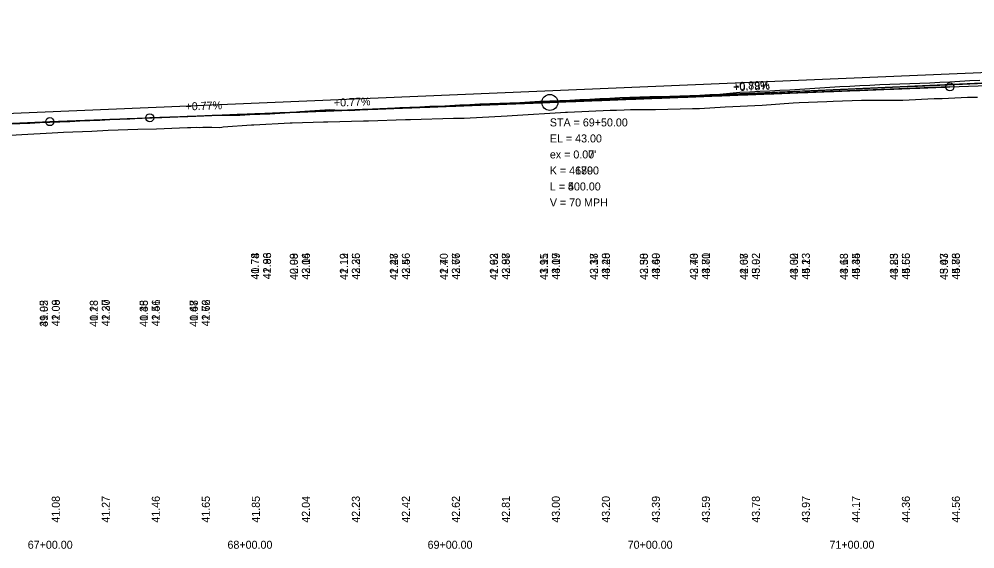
# Model space of a CAD drawing. Extents: x 3880794 to 3915434, y 287517 to 300173.
# Drawn here: x 3887223 to 3887700.8, y 296519.7 to 296784.4 of the extents above; entities that cross this region are included whole.
import ezdxf

# ---------------------------------------------------------------- set-up
doc = ezdxf.new("R2010")
doc.units = 0
for name, color, linetype in [('Level 1', 7, 'Continuous'), ('Level 2', 7, 'Continuous'), ('Level 30', 7, 'Continuous'), ('Level 31', 7, 'Continuous'), ('Level 32', 7, 'Continuous')]:
    doc.layers.add(name, color=color, linetype=linetype)

msp = doc.modelspace()

# ---------------------------------------------------------------- linework, layer by layer
at = {"layer": 'Level 1'}
for p, q in [((3887738.3, 296753.87), (3887492.29, 296742.93)), ((3887688.3, 296750.53), (3887738.3, 296752.48)), ((3887688.3, 296750.53), (3887492.29, 296742.91)), ((3887238.3, 296733.14), (3887484.3, 296742.6)), ((3887288.3, 296735.06), (3887484.3, 296742.6)), ((3886713.3, 296712.95), (3887288.3, 296735.06)), ((3886763.3, 296714.87), (3887238.3, 296733.14))]:
    msp.add_line(p, q, dxfattribs=at)
for points in [[(3887521.59, 296738.95), (3887525.37, 296739.11), (3887528.7, 296739.16), (3887541.06, 296739.28), (3887559.54, 296739.69), (3887563.11, 296739.73), (3887576.02, 296740.5), (3887579.85, 296740.74), (3887594.39, 296741.43), (3887609.96, 296742.54), (3887613.02, 296742.73), (3887626.71, 296743.21), (3887629.88, 296743.39), (3887644.18, 296743.85), (3887647.21, 296743.85), (3887661.54, 296743.9), (3887664.74, 296743.91), (3887680.5, 296744.65), (3887684.5, 296744.72), (3887697.12, 296745.32), (3887702.04, 296745.42)], [(3887215.89, 296726.2), (3887224.27, 296726.73), (3887239.4, 296727.56), (3887245.2, 296727.92), (3887259.26, 296728.43), (3887267.48, 296728.93), (3887282.24, 296729.38), (3887291.65, 296729.55), (3887303.06, 296730), (3887307.21, 296730.17), (3887308.82, 296730.29), (3887311.81, 296730.44), (3887313.02, 296730.14), (3887314.82, 296730.34), (3887316.18, 296730.38), (3887319.27, 296730.33), (3887323.29, 296730.24), (3887324.28, 296730.33), (3887324.99, 296730.5), (3887339.06, 296731.51), (3887340.27, 296731.58), (3887358.47, 296732.47), (3887359.53, 296732.51), (3887375.16, 296733.11), (3887376.6, 296732.99), (3887376.92, 296732.98), (3887377.28, 296732.98), (3887395.12, 296733.56), (3887397.71, 296733.58), (3887416.2, 296734.25), (3887418.61, 296734.25), (3887440.14, 296734.81), (3887442.95, 296734.85), (3887445.4, 296734.94), (3887466.9, 296736.07), (3887469.46, 296736.2), (3887472.12, 296736.32), (3887493.63, 296737.66), (3887496.17, 296737.89), (3887497.14, 296737.95), (3887518.43, 296738.82), (3887521.59, 296738.95)]]:
    msp.add_lwpolyline(points, dxfattribs=at)
msp.add_circle((3887488.3, 296742.76), 4, dxfattribs=at)
msp.add_circle((3887488.3, 296742.76), 4, dxfattribs=at)
for points in [[(3887238.3, 296733.14), (3887248.3, 296733.53), (3887258.3, 296733.91), (3887268.3, 296734.3), (3887278.3, 296734.69), (3887288.3, 296735.08), (3887298.3, 296735.47), (3887308.3, 296735.86), (3887318.3, 296736.26), (3887328.3, 296736.65), (3887338.3, 296737.05), (3887348.3, 296737.44), (3887358.3, 296737.84), (3887368.3, 296738.24), (3887378.3, 296738.64), (3887388.3, 296739.05), (3887398.3, 296739.45), (3887408.3, 296739.85), (3887418.3, 296740.26), (3887428.3, 296740.67), (3887438.3, 296741.07), (3887448.3, 296741.48), (3887458.3, 296741.89), (3887468.3, 296742.3), (3887478.3, 296742.72), (3887488.3, 296743.13), (3887498.3, 296743.55), (3887508.3, 296743.96), (3887518.3, 296744.38), (3887528.3, 296744.8), (3887538.3, 296745.22), (3887548.3, 296745.64), (3887558.3, 296746.06), (3887568.3, 296746.49), (3887578.3, 296746.91), (3887588.3, 296747.34), (3887598.3, 296747.76), (3887608.3, 296748.19), (3887618.3, 296748.62), (3887628.3, 296749.05), (3887638.3, 296749.48), (3887648.3, 296749.92), (3887658.3, 296750.35), (3887668.3, 296750.79), (3887678.3, 296751.22), (3887688.3, 296751.66), (3887698.3, 296752.1), (3887708.3, 296752.54), (3887718.3, 296752.98), (3887728.3, 296753.42), (3887738.3, 296753.87)], [(3887288.3, 296735.06), (3887296.3, 296735.37), (3887304.3, 296735.68), (3887312.3, 296735.99), (3887320.3, 296736.3), (3887328.3, 296736.6), (3887336.3, 296736.91), (3887344.3, 296737.22), (3887352.3, 296737.53), (3887360.3, 296737.84), (3887368.3, 296738.15), (3887376.3, 296738.45), (3887384.3, 296738.76), (3887392.3, 296739.07), (3887400.3, 296739.38), (3887408.3, 296739.69), (3887416.3, 296740), (3887424.3, 296740.31), (3887432.3, 296740.61), (3887440.3, 296740.92), (3887448.3, 296741.23), (3887456.3, 296741.54), (3887464.3, 296741.85), (3887472.3, 296742.16), (3887480.3, 296742.47), (3887488.3, 296742.78), (3887496.3, 296743.09), (3887504.3, 296743.4), (3887512.3, 296743.71), (3887520.3, 296744.02), (3887528.3, 296744.33), (3887536.3, 296744.64), (3887544.3, 296744.95), (3887552.3, 296745.26), (3887560.3, 296745.57), (3887568.3, 296745.88), (3887576.3, 296746.19), (3887584.3, 296746.5), (3887592.3, 296746.81), (3887600.3, 296747.12), (3887608.3, 296747.43), (3887616.3, 296747.74), (3887624.3, 296748.05), (3887632.3, 296748.36), (3887640.3, 296748.67), (3887648.3, 296748.98), (3887656.3, 296749.29), (3887664.3, 296749.6), (3887672.3, 296749.91), (3887680.3, 296750.22), (3887688.3, 296750.53)]]:
    msp.add_spline(points, degree=3, dxfattribs=at)
at = {"layer": 'Level 2'}
msp.add_line((3886763.3, 296718.25), (3888338.3, 296784.36), dxfattribs=at)
for points in [[(3887538.3, 296745.67), (3887543.3, 296745.69), (3887548.3, 296745.81), (3887553.3, 296746), (3887558.3, 296746.2), (3887563.3, 296746.42), (3887568.3, 296746.66), (3887573.3, 296746.91), (3887578.3, 296747.39), (3887583.3, 296747.79), (3887588.3, 296748.09), (3887593.3, 296748.35), (3887598.3, 296748.61), (3887603.3, 296748.87), (3887608.3, 296749.03), (3887613.3, 296749.34), (3887618.3, 296749.67), (3887623.3, 296750), (3887628.3, 296750.33), (3887633.3, 296750.64), (3887638.3, 296750.9), (3887643.3, 296751.17), (3887648.3, 296751.43), (3887653.3, 296751.68), (3887658.3, 296751.9), (3887663.3, 296752.03), (3887668.3, 296752.16), (3887673.3, 296752.29), (3887678.3, 296752.55), (3887683.3, 296752.82), (3887688.3, 296753.1), (3887693.3, 296753.37), (3887698.3, 296753.66), (3887703.3, 296753.88)], [(3887218.3, 296732.04), (3887223.3, 296732.23), (3887228.3, 296732.46), (3887233.3, 296732.66), (3887238.3, 296732.87), (3887243.3, 296733.07), (3887248.3, 296733.27), (3887253.3, 296733.48), (3887258.3, 296733.7), (3887263.3, 296733.92), (3887268.3, 296734.14), (3887273.3, 296734.36), (3887278.3, 296734.62), (3887283.3, 296734.88), (3887288.3, 296735.14), (3887293.3, 296735.36), (3887298.3, 296735.46), (3887303.3, 296735.67), (3887308.3, 296735.88), (3887313.3, 296736.09), (3887318.3, 296736.29), (3887323.3, 296736.33), (3887328.3, 296736.36), (3887333.3, 296736.38), (3887338.3, 296736.64), (3887343.3, 296736.87), (3887348.3, 296737.09), (3887353.3, 296737.38), (3887358.3, 296737.79), (3887363.3, 296738.2), (3887368.3, 296738.56), (3887373.3, 296738.85), (3887378.3, 296739.13), (3887383.3, 296738.91), (3887388.3, 296738.69), (3887393.3, 296739.11), (3887398.3, 296739.4), (3887403.3, 296739.67), (3887408.3, 296739.89), (3887413.3, 296740.13), (3887418.3, 296740.36), (3887423.3, 296740.6), (3887428.3, 296740.8), (3887433.3, 296740.96), (3887438.3, 296741.24), (3887443.3, 296741.51), (3887448.3, 296741.77), (3887453.3, 296742.02), (3887458.3, 296742.22), (3887463.3, 296742.42), (3887468.3, 296742.58), (3887473.3, 296742.66), (3887478.3, 296743), (3887483.3, 296743.34), (3887488.3, 296743.5), (3887493.3, 296743.66), (3887498.3, 296743.83), (3887503.3, 296744.17), (3887508.3, 296744.45), (3887513.3, 296744.68), (3887518.3, 296744.91), (3887523.3, 296745.14), (3887528.3, 296745.34), (3887533.3, 296745.54), (3887538.3, 296745.67)]]:
    msp.add_lwpolyline(points, dxfattribs=at)
at = {"layer": 'Level 31'}
for centre in [(3887688.3, 296750.53), (3887238.3, 296733.14), (3887288.3, 296735.06)]:
    msp.add_circle(centre, 2, dxfattribs=at)

# ---------------------------------------------------------------- texts
at = {"layer": 'Level 2'}
for s, p in [('42.93', (3887348.92, 296654.38)), ('43.14', (3887368.3, 296654.19)), ('43.35', (3887393.3, 296654.19)), ('43.56', (3887418.3, 296654.19)), ('43.77', (3887443.3, 296654.19)), ('43.98', (3887468.3, 296654.19)), ('44.19', (3887493.3, 296654.19)), ('44.40', (3887518.3, 296654.19)), ('44.60', (3887543.3, 296654.19)), ('44.81', (3887568.3, 296654.19)), ('45.02', (3887593.3, 296654.19)), ('45.23', (3887618.3, 296654.19)), ('45.44', (3887643.3, 296654.19)), ('45.65', (3887668.3, 296654.19)), ('45.86', (3887693.3, 296654.19)), ('42.09', (3887243.3, 296630.87)), ('42.30', (3887268.3, 296630.87)), ('42.51', (3887293.3, 296630.87)), ('42.72', (3887318.3, 296630.87))]:
    msp.add_text(s, height=4, rotation=90, dxfattribs=at).set_placement(p)
for s, p in [('67+00.00', (3887227.27, 296519.76)), ('68+00.00', (3887327.12, 296519.76)), ('69+00.00', (3887427.18, 296519.76)), ('70+00.00', (3887527.21, 296519.76)), ('71+00.00', (3887628.09, 296519.76))]:
    msp.add_text(s, height=4, dxfattribs=at).set_placement(p)
at = {"layer": 'Level 30'}
for s, p in [('40.74', (3887342.92, 296654.23)), ('40.98', (3887362.3, 296654.04)), ('41.12', (3887387.3, 296654.04)), ('41.28', (3887412.3, 296654.04)), ('41.40', (3887437.3, 296654.04)), ('41.62', (3887462.3, 296654.04)), ('41.91', (3887487.3, 296654.04)), ('42.17', (3887512.3, 296654.04)), ('42.30', (3887537.3, 296654.04)), ('42.40', (3887562.3, 296654.04)), ('42.68', (3887587.3, 296654.04)), ('43.00', (3887612.3, 296654.04)), ('43.18', (3887637.3, 296654.04)), ('43.23', (3887662.3, 296654.04)), ('43.43', (3887687.3, 296654.04)), ('39.95', (3887237.3, 296630.63)), ('40.18', (3887262.3, 296630.63)), ('40.35', (3887287.3, 296630.63)), ('40.48', (3887312.3, 296630.63))]:
    msp.add_text(s, height=4, rotation=90, dxfattribs=at).set_placement(p)
for s, p in [('67+00.00', (3887227.27, 296519.76)), ('67+00.00', (3887227.27, 296519.76)), ('67+00.00', (3887227.27, 296519.76)), ('68+00.00', (3887327.12, 296519.76)), ('68+00.00', (3887327.12, 296519.76)), ('68+00.00', (3887327.12, 296519.76)), ('69+00.00', (3887427.18, 296519.76)), ('69+00.00', (3887427.18, 296519.76)), ('69+00.00', (3887427.18, 296519.76)), ('70+00.00', (3887527.21, 296519.76)), ('70+00.00', (3887527.21, 296519.76)), ('70+00.00', (3887527.21, 296519.76)), ('71+00.00', (3887628.09, 296519.76)), ('71+00.00', (3887628.09, 296519.76)), ('71+00.00', (3887628.09, 296519.76))]:
    msp.add_text(s, height=4, dxfattribs=at).set_placement(p)
at = {"layer": 'Level 31'}
for s, rotation, p in [('+0.89%', 2.5448, (3887579.96, 296748.84)), ('+0.78%', 2.227, (3887580.09, 296748.33)), ('+0.77%', 2.2026, (3887306.21, 296738.68)), ('+0.77%', 2.2026, (3887380.39, 296740.61)), ('+0.77%', 2.2026, (3887380.39, 296740.61)), ('41.86', 90, (3887348.92, 296654.38)), ('42.06', 90, (3887368.3, 296654.19)), ('42.26', 90, (3887393.3, 296654.19)), ('42.46', 90, (3887418.3, 296654.19)), ('42.66', 90, (3887443.3, 296654.19)), ('42.87', 90, (3887468.3, 296654.19)), ('43.07', 90, (3887493.3, 296654.19)), ('43.28', 90, (3887518.3, 296654.19)), ('43.49', 90, (3887543.3, 296654.19)), ('43.70', 90, (3887568.3, 296654.19)), ('43.92', 90, (3887593.3, 296654.19)), ('44.13', 90, (3887618.3, 296654.19)), ('44.35', 90, (3887643.3, 296654.19)), ('44.56', 90, (3887668.3, 296654.19)), ('44.78', 90, (3887693.3, 296654.19)), ('41.08', 90, (3887243.3, 296630.87)), ('41.27', 90, (3887268.3, 296630.87)), ('41.46', 90, (3887293.3, 296630.87)), ('41.66', 90, (3887318.3, 296630.87)), ('41.08', 90, (3887243.3, 296532.76)), ('41.27', 90, (3887268.3, 296532.76)), ('41.46', 90, (3887293.3, 296532.76)), ('41.65', 90, (3887318.3, 296532.76)), ('41.85', 90, (3887343.3, 296532.76)), ('42.04', 90, (3887368.3, 296532.76)), ('42.23', 90, (3887393.3, 296532.76)), ('42.42', 90, (3887418.3, 296532.76)), ('42.62', 90, (3887443.3, 296532.76)), ('42.81', 90, (3887468.3, 296532.76)), ('43.00', 90, (3887493.3, 296532.76)), ('43.20', 90, (3887518.3, 296532.76)), ('43.39', 90, (3887543.3, 296532.76)), ('43.59', 90, (3887568.3, 296532.76)), ('43.78', 90, (3887593.3, 296532.76)), ('43.97', 90, (3887618.3, 296532.76)), ('44.17', 90, (3887643.3, 296532.76)), ('44.36', 90, (3887668.3, 296532.76)), ('44.56', 90, (3887693.3, 296532.76))]:
    msp.add_text(s, height=4, rotation=rotation, dxfattribs=at).set_placement(p)
for s, p in [('STA = 69+50.00', (3887488.3, 296730.76)), ('STA = 69+50.00', (3887488.3, 296730.76)), ('EL = 43.00', (3887488.3, 296722.76)), ('EL = 43.00', (3887488.3, 296722.76)), ("ex = 0.07'", (3887488.3, 296714.76)), ("ex = 0.00'", (3887488.3, 296714.76)), ('K = 4179', (3887488.3, 296706.76)), ('K = 46800', (3887488.3, 296706.76)), ('L = 500.00', (3887488.3, 296698.76)), ('L = 400.00', (3887488.3, 296698.76)), ('V = 70 MPH', (3887488.3, 296690.76))]:
    msp.add_text(s, height=4, dxfattribs=at).set_placement(p)
at = {"layer": 'Level 32'}
for s, p in [('41.78', (3887342.92, 296654.23)), ('42.09', (3887362.3, 296654.04)), ('42.19', (3887387.3, 296654.04)), ('42.47', (3887412.3, 296654.04)), ('42.70', (3887437.3, 296654.04)), ('42.93', (3887462.3, 296654.04)), ('43.15', (3887487.3, 296654.04)), ('43.38', (3887512.3, 296654.04)), ('43.58', (3887537.3, 296654.04)), ('43.73', (3887562.3, 296654.04)), ('44.07', (3887587.3, 296654.04)), ('44.32', (3887612.3, 296654.04)), ('44.63', (3887637.3, 296654.04)), ('44.85', (3887662.3, 296654.04)), ('45.07', (3887687.3, 296654.04)), ('41.02', (3887237.3, 296630.63)), ('41.23', (3887262.3, 296630.63)), ('41.48', (3887287.3, 296630.63)), ('41.67', (3887312.3, 296630.63))]:
    msp.add_text(s, height=4, rotation=90, dxfattribs=at).set_placement(p)

doc.saveas('drawing.dxf')
